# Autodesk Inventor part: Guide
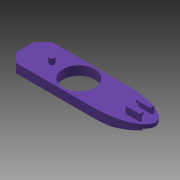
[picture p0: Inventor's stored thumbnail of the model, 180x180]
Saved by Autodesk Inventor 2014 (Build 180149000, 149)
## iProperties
Created: 2008-06
Part Number: Guide
Document SubType Name: Modeling
Designer: tangg
Density: 0.94 g/cm^3
Mass: 82.2056 g
Surface Area: 237.47 cm^2
Volume: 82.2056 cm^3
Stock Number: Guide
Material: UHMW, Black
Appearance: Violet
Author: tangg
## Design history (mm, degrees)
sketch "Sketch1"
  geometry: L1 (107.721, 0)-(-76.2, 0); L2 (-76.2, 0)-(-76.2, -12.7); L3 (-76.2, -12.7)-(69.621, -12.7); L4 (107.721, -6.35)-(107.721, 0); L5 (107.721, -6.35)-(69.621, -12.7); 1 further point
  constraints: 10 end point, 1 point on line, 1 vertical
  dimensions: "d19" = 183.92109 distance of L1.start L1.end; "d20" = 76.2 distance from line of point (0, 0) L2; "d21" = 12.7 distance of L1.end L2.end; "d22" = 38.1 horizontal distance of L4.start L3.end
extrude "Extrusion2" new body sketch "Sketch1" distance "d2" = 25.4; taper "d3" = 0 deg
sketch "Sketch2"
  geometry: C1 r 22.5 at (76.2, 0); 1 further point
  constraints: 1 centre point, 1 coincident
  dimensions: "d25" = 45 diameter of C1
extrude "Extrusion3" cut sketch "Sketch2" stored distance "d4" = 12.7; taper "d5" = 0 deg
mirror "Mirror1"
sketch "Sketch4"
  geometry: L1 (-36.784, 25.4)-(220.705, 25.4) reference; C1 r 3.81 at (38.1, 25.4); 1 further point
  constraints: 1 centre point, 1 point on line
  dimensions: "d13" = 7.62 diameter of C1; "d39" = 38.1 distance of C1.centre point (76.2, 25.4)
extrude "Extrusion5" join sketch "Sketch4" distance "d8" = 7.62; taper "d9" = 0 deg
workplane "Work Plane1"
sketch "Sketch10"
  geometry: L1 (-69.621, 36.625)-(38.1, 36.625); L2 (-69.621, 14.175)-(38.1, 14.175); L3 (-69.621, 36.625)-(-69.621, 14.175); L4 (38.1, 0)-(38.1, 50.8) reference; L5 (38.1, 36.625)-(38.1, 14.175); A1 r 11.225 centre (-69.621, 25.4) between (-69.621, 36.625) and (-69.621, 14.175); 1 further point
  constraints: 8 end point, 4 point on circle, 3 point on line, 1 centre point, 1 horizontal
extrude "Extrusion11" cut sketch "Sketch10" stored distance "d32" = 15.24; taper "d33" = 0 deg
workplane "Work Plane4"
sketch "Sketch5"
  geometry: L1 (-1.587, -10.238)-(9.525, -10.238); L2 (9.525, -10.238)-(9.525, 10.238); L3 (9.525, 10.238)-(-1.588, 10.238); L4 (-1.588, 10.238)-(-1.587, -10.238); L5 (9.525, -7.62)-(0, -7.62); L6 (0, -7.62)-(0, 7.62); L7 (0, 7.62)-(9.525, 7.62); L8 (9.525, 7.62)-(9.525, -7.62); L9 (0, 25.4)-(0, -25.4) reference; L10 (9.525, -7.62)-(6.5, -7.62); L11 (6.5, -7.62)-(6.5, -4.62); L12 (6.5, -4.62)-(9.525, -4.62); L13 (9.525, -4.62)-(9.525, -7.62); L14 (9.525, 7.62)-(6.5, 7.62); L15 (6.5, 7.62)-(6.5, 4.62); L16 (6.5, 4.62)-(9.525, 4.62); L17 (9.525, 4.62)-(9.525, 7.62); 3 further points
  constraints: 32 end point, 3 midpoint, 1 collinear, 1 horizontal alignment, 1 point on line
  dimensions: "d14" = 15.24 distance between parallel lines of L7 L5; "d50" = 6.5 distance between parallel lines of L6 L11; "d51" = 3 distance between parallel lines of L10 L12; "d52" = 3 distance between parallel lines of L7 L16
extrude "Extrusion6" join sketch "Sketch5" distance "d11" = 20; taper "d12" = 0 deg
fillet "Fillet1" dims "d47" = 0.635
chamfer "Chamfer1" distance "d40" = 12.7; stored, may be unused: second distance "d41" = 3.175, angle "d42" = 45 deg
sketch "Sketch11"
  geometry: L1 (-5.08, 11.225)-(-12.7, 11.225) reference; L2 (-12.7, -11.225)-(-5.08, -11.225) reference; L3 (-12.7, 11.225)-(-6.35, 11.225) reference; L4 (-6.35, 11.225)-(-5.08, 11.225) reference; L5 (-5.08, 11.225)-(-5.08, -11.225) reference; L6 (-6.35, -11.225)-(-12.7, -11.225) reference; C1 r 2.54 at (-15.875, 0); A1 r 11.377 centre (-10.848, 0) between (-12.7, 11.225) and (-12.7, -11.225); 3 further points; 2 other entities
  constraints: 2 centre point, 2 point on circle, 2 other
  dimensions: "d48" = 3.175 distance of point (-12.7, 0) C1.centre; "d49" = 5.08 diameter of C1
extrude "Extrusion12" join sketch "Sketch11" stored distance "d37" = 12.7; taper "d38" = 0 deg
sketch "Sketch12"
  geometry: L1 (-171.221, 50.8)-(0, 50.8) reference; L2 (0, 0)-(0, 50.8) reference; L3 (-171.221, 0)-(0, 0) reference; L4 (0, 25.4)-(-107.721, 25.4); 3 further points; 1 other entity
  constraints: 3 point on line, 2 end point, 1 midpoint, 5 other
extrude "Extrusion13" cut sketch "Sketch12" stored distance "d43" = 25.4; taper "d44" = 0 deg
body "Solid1"
other parameters: "d10" = 76.2, "d34" = 63.5
